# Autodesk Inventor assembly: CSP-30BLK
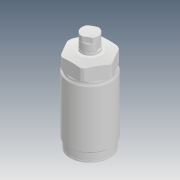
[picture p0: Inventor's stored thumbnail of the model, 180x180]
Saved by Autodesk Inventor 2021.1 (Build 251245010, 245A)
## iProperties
Created: 2019-01
Part Number: CSP-30BLK
Description: STEP AP203
Document SubType Name: Assembly
Designer: user
Title: CSP-030-K×é×°Í¼£¨³õÊ¼×´Ì¬£©.STEP
Revision Number: ÈÎºÎ
Sending System: SolidWorks 2014
Preprocessor: SwSTEP 2.0
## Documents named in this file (4)
- D:\Vault_2016\Projekty\Clamptek\Hydraulic\CSP-P-K\CSP-30KP\Inventor\CSP-30BLK\CSP-30BLK.iam
- D:\Vault_2016\Projekty\Clamptek\Hydraulic\CSP-P-K\CSP-30KP\Inventor\CSP-30BLK\CSP-030-K±¾Ìå£¨³õÊ¼£©.ipt
- D:\Vault_2016\Projekty\Clamptek\Hydraulic\CSP-P-K\CSP-30KP\Inventor\CSP-30BLK\CSP-030»îÈû¸Ë.ipt
- D:\Vault_2016\Projekty\Clamptek\Hydraulic\CSP-P-K\CSP-30KP\Inventor\CSP-30BLK\CSP-030Ô²Í·ÂÝË¨.ipt
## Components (3 placed, 3 different names)
1. CSP-030-K±¾Ìå£¨³õÊ¼£©_1
2. CSP-030»îÈû¸Ë_2
3. CSP-030Ô²Í·ÂÝË¨_3
